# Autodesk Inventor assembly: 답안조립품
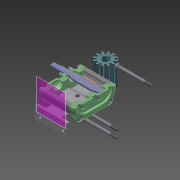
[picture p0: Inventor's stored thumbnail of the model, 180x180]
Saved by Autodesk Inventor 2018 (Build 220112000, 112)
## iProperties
Created: 2023-06
Part Number: 답안조립품
Material: 일반
Document SubType Name: Assembly
Designer: 강의실01
Author: 강의실01
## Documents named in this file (8)
- C:\Users\kimgi\Desktop\730606V1010\답안조립품.iam
- C:\Users\kimgi\Desktop\730606V1010\본체.ipt
- C:\Users\kimgi\Desktop\730606V1010\앞커버.ipt
- C:\Users\kimgi\Desktop\730606V1010\뒷커버.ipt
- C:\Users\kimgi\Desktop\730606V1010\샤프트.ipt
- C:\Users\kimgi\Desktop\730606V1010\메인 드라이브 기어.ipt
- C:\Users\kimgi\Desktop\730606V1010\묻힘키 6x6x40.ipt
- C:\Users\kimgi\Desktop\730606V1010\육각 소켓 머리 볼트 M8 x 100.ipt
